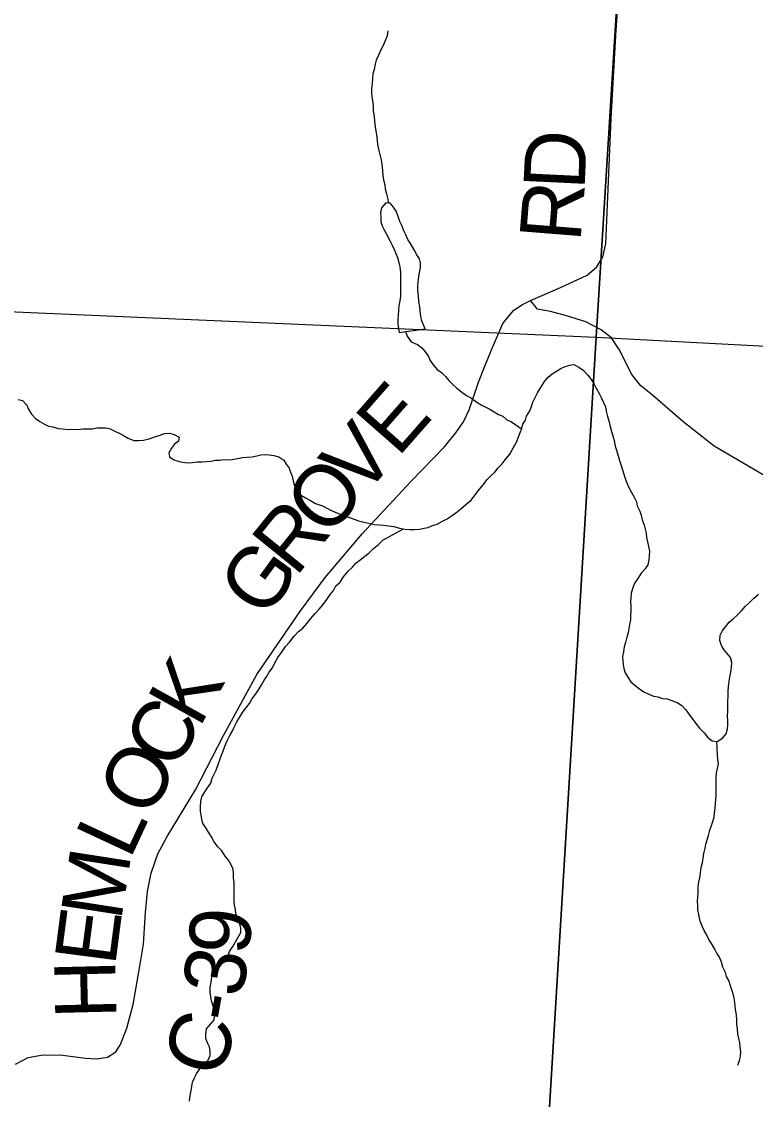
# Model space of a CAD drawing. Extents: x -20.2 to 34, y 0 to 22.
# Drawn here: x 6.507 to 7.189, y 19.304 to 20.305 of the extents above; entities that cross this region are included whole.
import ezdxf

# ---------------------------------------------------------------- set-up
doc = ezdxf.new("R2010")
doc.units = 0
for name, color, linetype in [('Default', 7, 'Continuous'), ('GM_X_County_Road', 7, 'Continuous'), ('GM_X_County_Road_Text', 7, 'Continuous'), ('GM_X_Minor_River', 7, 'Continuous'), ('GM_X_Section', 7, 'Continuous'), ('GM_X_Township_Road', 7, 'Continuous')]:
    doc.layers.add(name, color=color, linetype=linetype)

msp = doc.modelspace()

# ---------------------------------------------------------------- linework, layer by layer
at = {"layer": 'Default'}
for points in [[(7.0959, 20.9), (6.0195, 20.9), (6.0189, 20.878), (6.0052, 20.4384), (5.9839, 20.0577), (7.0409, 20.0115)], [(8.1484, 20.9), (7.0959, 20.9), (7.0409, 20.0115), (8.0972, 19.9556)]]:
    msp.add_lwpolyline(points, close=True, dxfattribs=at)
at = {"layer": 'GM_X_County_Road'}
for points in [[(6.98, 20.0456), (7.0079, 20.0576), (7.0326, 20.0693), (7.0415, 20.0769), (7.0471, 20.0861), (7.0497, 20.0982), (7.0547, 20.2144), (7.0595, 20.2967), (7.0625, 20.3401)], [(6.502, 19.3368), (6.5135, 19.343), (6.5258, 19.3452), (6.5434, 19.3455), (6.5669, 19.3424), (6.5773, 19.3419), (6.5874, 19.3433), (6.5949, 19.3483), (6.5994, 19.3553), (6.6053, 19.3702), (6.611, 19.3924), (6.6173, 19.4278), (6.6206, 19.4484), (6.6224, 19.4777), (6.6243, 19.4973), (6.6277, 19.5141), (6.6339, 19.532), (6.6428, 19.5482), (6.6689, 19.5916), (6.6949, 19.6418), (6.726, 19.6986), (6.7663, 19.7577), (6.7893, 19.7885), (6.8237, 19.8291), (6.8693, 19.8781), (6.8999, 19.9094), (6.9105, 19.9229), (6.9178, 19.933), (6.9231, 19.9442), (6.9315, 19.9699), (6.9374, 19.9848), (6.9438, 19.9999), (6.9542, 20.0242), (6.964, 20.0363), (6.9718, 20.0416), (6.98, 20.0456)]]:
    msp.add_lwpolyline(points, dxfattribs=at)
at = {"layer": 'GM_X_Minor_River'}
for points in [[(6.8475, 20.2959), (6.8468, 20.2914), (6.8454, 20.2875), (6.8435, 20.283), (6.8409, 20.2784), (6.8387, 20.2734), (6.8368, 20.2688), (6.8358, 20.265), (6.8347, 20.26), (6.8336, 20.2559), (6.8333, 20.2517), (6.8329, 20.2471), (6.8322, 20.2425), (6.8323, 20.2384), (6.8327, 20.2346), (6.8335, 20.2293), (6.8339, 20.2255), (6.834, 20.2217), (6.8348, 20.2163), (6.8352, 20.2122), (6.8357, 20.2069), (6.8365, 20.2027), (6.8373, 20.1978), (6.8377, 20.1932), (6.8382, 20.189), (6.839, 20.1849), (6.8402, 20.1811), (6.8414, 20.1761), (6.8418, 20.172), (6.8426, 20.1663), (6.843, 20.1617), (6.8435, 20.1576), (6.8447, 20.153), (6.8451, 20.1492), (6.8463, 20.1447), (6.8471, 20.1409), (6.8479, 20.1371), (6.8483, 20.1361)], [(6.8821, 20.0193), (6.8788, 20.0273), (6.878, 20.0311), (6.8776, 20.0356), (6.8771, 20.0398), (6.8763, 20.0447), (6.8759, 20.05), (6.8754, 20.0546), (6.8754, 20.0588), (6.8757, 20.0626), (6.8764, 20.0675), (6.8768, 20.0717), (6.8778, 20.0763), (6.8778, 20.0805), (6.877, 20.0843), (6.8743, 20.088), (6.872, 20.0926), (6.8685, 20.0986), (6.8661, 20.1024), (6.8642, 20.1065), (6.8623, 20.1103), (6.8607, 20.1145), (6.8587, 20.119), (6.8572, 20.1235), (6.8552, 20.1284), (6.8529, 20.1322), (6.8498, 20.136), (6.8456, 20.1363), (6.8415, 20.1317), (6.8408, 20.1271), (6.8409, 20.1226), (6.8409, 20.1188), (6.8421, 20.115), (6.844, 20.1112), (6.8463, 20.1071), (6.8495, 20.1014), (6.8514, 20.0969), (6.8533, 20.0931), (6.8549, 20.0893), (6.8565, 20.0855), (6.8577, 20.081), (6.8585, 20.0768), (6.8593, 20.0715), (6.8593, 20.0669), (6.8594, 20.0631), (6.8594, 20.0586), (6.8591, 20.0544), (6.8592, 20.0498), (6.8585, 20.0453), (6.8578, 20.0407), (6.8574, 20.0365), (6.8571, 20.0323), (6.8568, 20.0281), (6.8568, 20.0236), (6.8573, 20.0198), (6.8581, 20.016), (6.8821, 20.0193)], [(6.8638, 20.0168), (6.8653, 20.0124), (6.8693, 20.0073), (6.8749, 20.0048), (6.8791, 20.0018), (6.8826, 19.9977), (6.8851, 19.9938), (6.8868, 19.9901), (6.8895, 19.986), (6.8934, 19.9815), (6.8972, 19.9789), (6.9011, 19.9751), (6.904, 19.9714), (6.9076, 19.968), (6.9114, 19.9642), (6.916, 19.9609), (6.9206, 19.9575), (6.9252, 19.9549), (6.9302, 19.9512), (6.934, 19.9489), (6.9378, 19.9471), (6.9416, 19.9452), (6.9462, 19.9422), (6.9501, 19.94), (6.9543, 19.9382), (6.9581, 19.9348), (6.9623, 19.9329), (6.9717, 19.9266)], [(6.9431, 19.8829), (6.9469, 19.8864), (6.9499, 19.8902), (6.9536, 19.8941), (6.9574, 19.8991), (6.9607, 19.9029), (6.963, 19.9071), (6.9652, 19.9109), (6.9671, 19.9148), (6.9689, 19.919), (6.9704, 19.9232), (6.9718, 19.927), (6.9729, 19.9308), (6.9752, 19.9346), (6.9763, 19.9384), (6.9792, 19.9434), (6.9807, 19.9472), (6.9822, 19.9514), (6.9844, 19.9556), (6.9863, 19.9599), (6.9904, 19.9664), (6.993, 19.9706), (6.9963, 19.9744), (7.0001, 19.9775), (7.0042, 19.9802), (7.008, 19.9825), (7.0122, 19.9845), (7.0163, 19.9857), (7.0201, 19.9861), (7.0247, 19.9839), (7.0289, 19.9809), (7.0331, 19.9764), (7.0362, 19.9723), (7.0389, 19.9681), (7.0409, 19.9643), (7.0436, 19.9594), (7.0455, 19.9557), (7.0475, 19.9515), (7.0494, 19.947), (7.0502, 19.9428), (7.0514, 19.9379), (7.0526, 19.9341), (7.0538, 19.9288), (7.055, 19.9242), (7.0562, 19.9201), (7.0578, 19.9144), (7.0586, 19.9106), (7.0598, 19.9068), (7.0614, 19.9015), (7.0625, 19.8973), (7.0641, 19.8924), (7.0653, 19.8886), (7.0665, 19.8845), (7.0677, 19.8803), (7.0692, 19.8765), (7.0708, 19.8728), (7.0735, 19.8682), (7.0758, 19.8637), (7.0782, 19.8588), (7.079, 19.855), (7.0813, 19.8501), (7.0825, 19.8463), (7.0837, 19.8421), (7.0853, 19.8372), (7.0865, 19.8334), (7.0873, 19.8296), (7.0877, 19.8258), (7.0885, 19.8217), (7.0893, 19.8175), (7.0905, 19.813), (7.0902, 19.8088), (7.0898, 19.805), (7.0887, 19.8004), (7.0865, 19.7966), (7.0828, 19.7927), (7.0794, 19.7877), (7.076, 19.7828), (7.0746, 19.7782), (7.0735, 19.774), (7.0732, 19.7698), (7.0728, 19.7656), (7.0729, 19.7618), (7.0729, 19.758), (7.0726, 19.7531), (7.0726, 19.7493), (7.0719, 19.7451), (7.0712, 19.7413), (7.0705, 19.7371), (7.0694, 19.7333), (7.068, 19.7283), (7.0669, 19.7241), (7.0662, 19.7196), (7.0654, 19.7154), (7.0655, 19.7116), (7.0659, 19.7078), (7.0667, 19.704), (7.0679, 19.7002), (7.0702, 19.696), (7.0729, 19.6919), (7.0772, 19.6882), (7.081, 19.6852)], [(6.5042, 19.9538), (6.5084, 19.9527), (6.5123, 19.9486), (6.5138, 19.9448), (6.5166, 19.9403), (6.5204, 19.9361), (6.5246, 19.9332), (6.5288, 19.9309), (6.5326, 19.9291), (6.5364, 19.9284), (6.5414, 19.9269), (6.5456, 19.9266), (6.5501, 19.9259), (6.5554, 19.9263)], [(6.5554, 19.9263), (6.56, 19.926), (6.5645, 19.9264), (6.5691, 19.9265), (6.5733, 19.9265), (6.5774, 19.9274), (6.5812, 19.9274), (6.5858, 19.9275), (6.5896, 19.9264), (6.5942, 19.9245), (6.5988, 19.9223), (6.6026, 19.9201), (6.6064, 19.9178), (6.6117, 19.9156), (6.6163, 19.9157), (6.6208, 19.9161), (6.6258, 19.9173), (6.6303, 19.9189), (6.6352, 19.9205), (6.6401, 19.9221), (6.6447, 19.9225), (6.6493, 19.9214), (6.6538, 19.9188), (6.6531, 19.915), (6.6494, 19.9123), (6.6468, 19.9085), (6.6441, 19.9043), (6.6449, 19.9005), (6.6488, 19.8979), (6.653, 19.8964), (6.6568, 19.8957), (6.6613, 19.895), (6.6659, 19.8954), (6.6704, 19.8958), (6.675, 19.8959), (6.6792, 19.8963), (6.6833, 19.8964), (6.6875, 19.8976), (6.6913, 19.8976), (6.6951, 19.8981), (6.6989, 19.8977), (6.7031, 19.8982), (6.708, 19.899), (6.7125, 19.8998), (6.7167, 19.9002), (6.7216, 19.9007), (6.7258, 19.9015), (6.7296, 19.9023), (6.7334, 19.9027), (6.7372, 19.9024), (6.7417, 19.9017), (6.7463, 19.9006), (6.7509, 19.8976), (6.7532, 19.8938), (6.7559, 19.8901), (6.7571, 19.8863), (6.7587, 19.8825), (6.7595, 19.8783), (6.761, 19.8738), (6.763, 19.8693), (6.7672, 19.8648), (6.771, 19.8625), (6.7756, 19.8599), (6.7802, 19.8573), (6.7867, 19.8551), (6.7909, 19.8529), (6.7947, 19.851), (6.7993, 19.8488), (6.8035, 19.8474), (6.8081, 19.8455), (6.8119, 19.8444), (6.8161, 19.8426), (6.8203, 19.8411), (6.8252, 19.84), (6.8298, 19.8389), (6.8347, 19.8379), (6.8393, 19.8375), (6.8438, 19.8372), (6.848, 19.8365), (6.853, 19.8358), (6.8583, 19.8344), (6.8632, 19.8333), (6.8678, 19.833), (6.8724, 19.833), (6.8769, 19.8335), (6.8811, 19.8343), (6.8849, 19.8351), (6.889, 19.8367), (6.8932, 19.8382), (6.8981, 19.8409), (6.9026, 19.8429), (6.9064, 19.8456), (6.9105, 19.8487), (6.9154, 19.8522), (6.9199, 19.8564), (6.9248, 19.8603), (6.9285, 19.8653), (6.9327, 19.8706), (6.9364, 19.8749), (6.9394, 19.8791), (6.9431, 19.8829)], [(6.7042, 19.514), (6.7038, 19.5178), (6.7022, 19.5219), (6.6995, 19.5261), (6.6964, 19.5299), (6.6933, 19.5348), (6.6898, 19.5385), (6.6864, 19.5434), (6.6837, 19.5479), (6.681, 19.5521), (6.679, 19.5559), (6.6759, 19.5604), (6.6747, 19.5642), (6.6743, 19.568), (6.6735, 19.5717), (6.6735, 19.5755), (6.6738, 19.5809), (6.6749, 19.5851), (6.6775, 19.5897), (6.6801, 19.5935), (6.6831, 19.5977), (6.6845, 19.6023), (6.6864, 19.6061), (6.6882, 19.6099), (6.6901, 19.6149), (6.6915, 19.6195), (6.693, 19.6237), (6.6949, 19.6283), (6.6963, 19.6321), (6.6985, 19.637), (6.7008, 19.642), (6.703, 19.6458), (6.7049, 19.6497), (6.7074, 19.6546), (6.7097, 19.6585), (6.7127, 19.6634), (6.7157, 19.6673), (6.719, 19.6715), (6.7212, 19.6757), (6.7239, 19.6795), (6.7272, 19.6838), (6.7298, 19.6884), (6.7324, 19.6926), (6.735, 19.6964), (6.7373, 19.7006), (6.7403, 19.7048), (6.7425, 19.7094), (6.7455, 19.7144), (6.7488, 19.719), (6.7526, 19.7244), (6.7563, 19.7286), (6.7604, 19.734), (6.7645, 19.7386), (6.7687, 19.7417), (6.7724, 19.7459), (6.7758, 19.7501), (6.7799, 19.7551), (6.7837, 19.7593), (6.7874, 19.7636), (6.7908, 19.7682), (6.7941, 19.7728), (6.7971, 19.7766), (6.7993, 19.7808), (6.8031, 19.7843), (6.8061, 19.7889), (6.8106, 19.7946), (6.8147, 19.7981), (6.8177, 19.8019), (6.8218, 19.805), (6.826, 19.8085), (6.8297, 19.8112), (6.8342, 19.8154), (6.8387, 19.8193), (6.8432, 19.8235), (6.847, 19.8255), (6.8512, 19.8278), (6.8619, 19.8336)], [(7.081, 19.6852), (7.0852, 19.6826), (7.0898, 19.6803), (7.094, 19.6785), (7.0982, 19.6778), (7.1024, 19.6763), (7.1069, 19.676), (7.1111, 19.6745), (7.1161, 19.6727), (7.1203, 19.6697), (7.1241, 19.6659), (7.1272, 19.6614), (7.1307, 19.6569), (7.1334, 19.6531), (7.1368, 19.6486), (7.1411, 19.6445), (7.1442, 19.6404), (7.1487, 19.637), (7.1533, 19.6363), (7.1582, 19.6394), (7.1616, 19.6436), (7.1627, 19.6482), (7.163, 19.652), (7.163, 19.6558), (7.1629, 19.66), (7.1632, 19.6645), (7.1632, 19.6695), (7.1631, 19.6737), (7.1634, 19.6782), (7.1634, 19.6828), (7.1637, 19.6873), (7.1644, 19.6923), (7.1648, 19.6961), (7.1658, 19.7007), (7.1665, 19.7052), (7.1669, 19.7098), (7.1657, 19.7143), (7.1626, 19.7181), (7.1595, 19.7219), (7.1572, 19.7256), (7.1556, 19.7302), (7.1559, 19.7351), (7.1578, 19.7389), (7.1608, 19.7428), (7.1642, 19.747), (7.1679, 19.7501), (7.1717, 19.7536), (7.1754, 19.7574), (7.1792, 19.7616), (7.1833, 19.7655), (7.187, 19.769), (7.1916, 19.7732)], [(7.1724, 19.336), (7.1739, 19.3402), (7.175, 19.344), (7.1753, 19.3485), (7.1745, 19.3527), (7.1741, 19.3569), (7.1733, 19.3607), (7.1725, 19.3652), (7.172, 19.3698), (7.1716, 19.3739), (7.1715, 19.3781), (7.1711, 19.3827), (7.1703, 19.3876), (7.1699, 19.3914), (7.1694, 19.3963), (7.1686, 19.4001), (7.1671, 19.405), (7.1655, 19.4096), (7.1639, 19.4145), (7.162, 19.4183), (7.1608, 19.4221), (7.1584, 19.427), (7.1573, 19.4315), (7.1553, 19.4361), (7.153, 19.4398), (7.151, 19.4436), (7.1479, 19.4489), (7.1456, 19.4527), (7.1433, 19.4572), (7.141, 19.461), (7.1394, 19.4651), (7.1374, 19.4697), (7.1362, 19.4757), (7.1354, 19.4803), (7.1354, 19.4841), (7.1349, 19.4882), (7.1353, 19.492), (7.1356, 19.4962), (7.1356, 19.5008), (7.1359, 19.5046), (7.137, 19.5099), (7.1377, 19.5145), (7.1384, 19.5194), (7.1395, 19.524), (7.1402, 19.5278), (7.1409, 19.5324), (7.142, 19.5373), (7.1427, 19.5412), (7.1438, 19.545), (7.1452, 19.5492), (7.1463, 19.5541), (7.1478, 19.5583), (7.1493, 19.5621), (7.1503, 19.5663), (7.1507, 19.5701), (7.1514, 19.5747), (7.1517, 19.5789), (7.152, 19.5827), (7.1524, 19.5865), (7.1523, 19.5903), (7.1523, 19.5945), (7.1522, 19.599), (7.1522, 19.6028), (7.1525, 19.6074), (7.1536, 19.6112), (7.1543, 19.6158), (7.1539, 19.6196), (7.1535, 19.6241), (7.1529, 19.6363)], [(6.6634, 19.3026), (6.6641, 19.3079), (6.6648, 19.3125), (6.6655, 19.3163), (6.6662, 19.3201), (6.6681, 19.3243), (6.6703, 19.3285), (6.6729, 19.3327), (6.6767, 19.3369), (6.6808, 19.3408), (6.6826, 19.345), (6.6826, 19.3488), (6.6818, 19.353), (6.6802, 19.3568), (6.6787, 19.3609), (6.6786, 19.3651), (6.6793, 19.3697), (6.6831, 19.3743), (6.6864, 19.3781), (6.6867, 19.3827), (6.6859, 19.388), (6.6851, 19.3918), (6.6839, 19.3956), (6.6831, 19.3993), (6.6827, 19.4039), (6.6827, 19.4081), (6.6834, 19.413), (6.6841, 19.4176), (6.6855, 19.4222), (6.6881, 19.4264), (6.6923, 19.4295), (6.696, 19.4329), (6.699, 19.4372), (6.7005, 19.4414), (6.7035, 19.446), (6.7061, 19.4506), (6.7087, 19.4548), (6.7109, 19.459), (6.7109, 19.4632), (6.7097, 19.4681), (6.7081, 19.4722), (6.7065, 19.4764), (6.7061, 19.4806), (6.7053, 19.4844), (6.7049, 19.4889), (6.7048, 19.4931), (6.7048, 19.4969), (6.7047, 19.5015), (6.7047, 19.5056), (6.7042, 19.5094), (6.7042, 19.514)]]:
    msp.add_lwpolyline(points, dxfattribs=at)
at = {"layer": 'GM_X_Section'}
for points in [[(7.0409, 20.0115), (6.9777, 18.9706), (5.9253, 19.026), (5.9839, 20.0577)], [(8.0972, 19.9556), (8.0404, 18.9117), (6.9777, 18.9706), (7.0409, 20.0115)]]:
    msp.add_lwpolyline(points, close=True, dxfattribs=at)
at = {"layer": 'GM_X_Township_Road'}
msp.add_lwpolyline([(7.2118, 19.8746), (7.1864, 19.8895), (7.1504, 19.9106), (7.1214, 19.9332), (7.0932, 19.9579), (7.0823, 19.9664), (7.074, 19.9771), (7.0621, 20.0003), (7.055, 20.011), (7.0456, 20.0183), (7.0312, 20.0259), (7.0134, 20.0314), (6.9985, 20.0355), (6.9864, 20.0375), (6.98, 20.0456)], dxfattribs=at)

# ---------------------------------------------------------------- texts
at = {"layer": 'GM_X_County_Road_Text'}
for s, rotation, p in [('D', 87.2506, (7.03, 20.1477)), ('R', 85.4444, (7.0262, 20.0992)), ('E', 48.733, (6.8568, 19.8993)), ('V', 48.7377, (6.8238, 19.8617)), ('O', 48.9364, (6.791, 19.8241)), ('R', 51.072, (6.762, 19.7882)), ('G', 53.9745, (6.7331, 19.7484)), ('K', 60.8884, (6.6724, 19.648)), ('C', 60.884, (6.6497, 19.6073)), ('O', 61.0101, (6.6255, 19.5636)), ('L', 65.0662, (6.608, 19.526)), ('M', 81.1543, (6.5998, 19.4691)), ('E', 82.5954, (6.5943, 19.4273)), ('9', 85.1876, (6.7185, 19.4373)), ('3', 80.3769, (6.712, 19.3976)), ('H', 91.3953, (6.5957, 19.3796)), ('-', 79.8144, (6.7077, 19.3741)), ('C', 72.7228, (6.692, 19.322))]:
    msp.add_text(s, height=0.0568, rotation=rotation, dxfattribs=at).set_placement(p)

doc.saveas('drawing.dxf')
